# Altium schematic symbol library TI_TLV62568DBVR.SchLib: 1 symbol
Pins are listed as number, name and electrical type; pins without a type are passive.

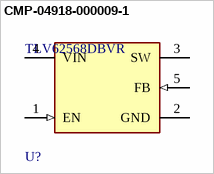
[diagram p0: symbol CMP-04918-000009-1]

## CMP-04918-000009-1
designator U?, comment TLV62568DBVR
IC REG BUCK ADJ 1A SOT23-5; Manufacturer: Texas Instruments; Number Of Outputs: 1; Max Supply Voltage: 5.5V; Nominal Supply Current: 35uA; Standoff Height: 0mm; Max Junction Temp: +125°C; Output Voltage: 0.6-5.5V; Max Duty Cycle: 100%; Output Type: AdjustableProgrammable; Min Supply Voltage: 2.5V; Switching Frequency: 1.5MHz
footprint FP-DBV0005A-MFG
footprint FP-DBV0005A-IPC_B
footprint FP-DBV0005A-IPC_C
footprint FP-DBV0005A-IPC_A
pins: 1 EN (in), 2 GND (power), 3 SW, 4 VIN (power), 5 FB (in)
